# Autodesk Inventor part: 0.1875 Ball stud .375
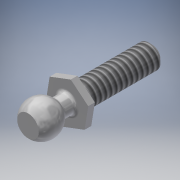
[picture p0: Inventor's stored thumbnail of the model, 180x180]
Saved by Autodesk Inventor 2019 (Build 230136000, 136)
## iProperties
Shininess: 70.0
Length Units: 11272
Angle Units: 11279
Time Units: 11290
Mass Units: 11286
Length Display Precision: 3
Angle Display Precision: 2
Compacted: True
Company: Autodesk
Created: 2000-12
Part Number: 0.1875 Ball stud .375
Document SubType Name: Modeling
Designer: Autodesk, Inc.
Project: Inventor Samples
User Status: IN PROGRESS
Density: 8.08 g/cm^3
Material: Stainless Steel
Mass: 0.939367 g
Surface Area: 1.892 cm^2
Volume: 0.116258 cm^3
Appearance: Steel
Density: 0.0
Volumn: 0.0
Area: 0.0
PropertySet Name: Model Information
Control State: 0
Master: False
Checked Out: False
Checked Out Date: 2018-05-30
Last Check In Date: 2018-05-30
Author: Autodesk, Inc.
Revision Number: A
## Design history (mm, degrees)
sketch "Sketch3"
  geometry: L1 (-1.183, 7.964)-(-3.755, 6.99); L2 (-3.755, 6.99)-(-4.197, 4.276); L3 (-4.197, 4.276)-(-2.068, 2.536); L4 (-2.068, 2.536)-(0.503, 3.51); L5 (0.503, 3.51)-(0.946, 6.224); L6 (0.946, 6.224)-(-1.183, 7.964); C1 r 2.381 at (-1.626, 5.25)
  constraints: 12 end point, 6 equal length, 6 tangent, 1 centre point, 1 parallel, 1 other
  dimensions: "d2" = 4.7625 diameter of C1
workaxis "Work Axis1"
extrude "Extrusion1" new body sketch "Sketch3" distance "d0" = 0.8128; taper "d1" = 0 deg
sketch "Sketch4"
  geometry: C1 r 1.08 at (-1.626, 5.25); 1 further point
  constraints: 1 centre point, 1 coincident
  dimensions: "d10" = 2.159 diameter of C1
extrude "Extrusion2" join sketch "Sketch4" distance "d11" = 3.175; taper "d12" = 0 deg
sketch "Sketch5"
  geometry: L1 (0, 2.064)-(0, -2.064); C1 r 1.08 at (0, 0) reference; A1 r 2.064 centre (0, 0) between (0, 2.064) and (0, -2.064)
  constraints: 2 end point, 2 point on circle, 1 centre point, 1 coincident, 1 midpoint, 1 vertical
  dimensions: "d13" = 4.1275 diameter of A1
revolve "Revolution1" sketch "Sketch5" stored, may be unused: angle "d14" = 90 deg
fillet "Fillet1" dims "d15" = 0.381
workplane "Work Plane2"
split "Split1"
sketch "Sketch7"
  geometry: C1 r 1.08 at (1.626, 5.25) reference; C2 r 1.422 at (1.626, 5.25)
  constraints: 1 centre point, 1 coincident
  dimensions: "d21" = 2.8448 diameter of C2
extrude "Extrusion3" join sketch "Sketch7" distance "d22" = 9.525; taper "d23" = 0 deg
chamfer "Chamfer1" distance "d24" = 0.381; stored, may be unused: second distance "d25" = 0.381, angle "d28" = 45 deg
thread "Thread1" dims "d26" = 25.4, "d27" = 0
body "Solid1"
other parameters: "d16" = 4.7625
